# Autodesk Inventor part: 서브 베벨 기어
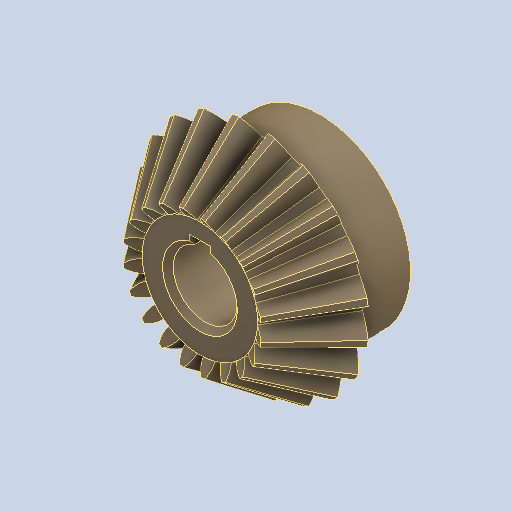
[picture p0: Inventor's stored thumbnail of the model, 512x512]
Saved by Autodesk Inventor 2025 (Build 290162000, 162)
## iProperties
Created: 2024-07
Part Number: 서브 베벨 기어
Material: 강철, 탄소
Document SubType Name: Modeling
Designer: hsj03
Density: 7.87 g/cm^3
Appearance: 기본값
Author: jhkim
Revision Number: 1
Sending System: Autodesk Inventor 2025
Preprocessor: ST-DEVELOPER v20
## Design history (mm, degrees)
node "복구된 형상1"
  node "스케치11"
feature "Solid1"
node "스케치10"
node "솔리드1"
